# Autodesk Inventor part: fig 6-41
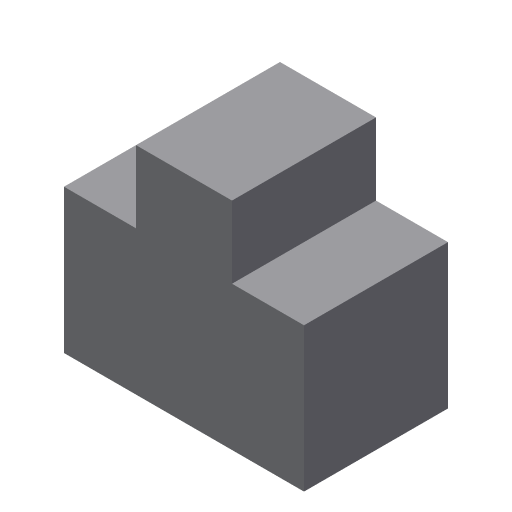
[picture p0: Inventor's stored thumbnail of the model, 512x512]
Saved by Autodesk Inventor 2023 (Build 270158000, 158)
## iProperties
Created: 2005-12
Part Number: fig 6-41
Document SubType Name: Modeling
Designer: CADCIM
Density: 1 g/cm^3
Material: Generic
Appearance: Default
Author: CADCIM
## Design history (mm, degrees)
sketch "Sketch1"
  geometry: L1 (10, 15)-(25, 15); L2 (25, 15)-(25, -15); L3 (25, -15)-(-25, -15); L4 (-25, -15)-(-25, 15); L5 (-25, 15)-(-10, 15); L6 (10, 15)-(10, 30); L7 (10, 30)-(-10, 30); L8 (-10, 30)-(-10, 15)
  constraints: 16 end point, 3 parallel, 3 perpendicular, 2 equal length, 1 collinear, 1 horizontal
  dimensions: "d0" = 50 distance of L2.end L3.end; "d2" = 30 distance of L1.end L2.end; "d3" = 15 distance of L1.start L1.end; "d11" = 15 distance of L7.end L5.end
extrude "Extrusion1" new body sketch "Sketch1" stored distance "d7" = 30; taper "d8" = 0 deg
body "Solid1"
